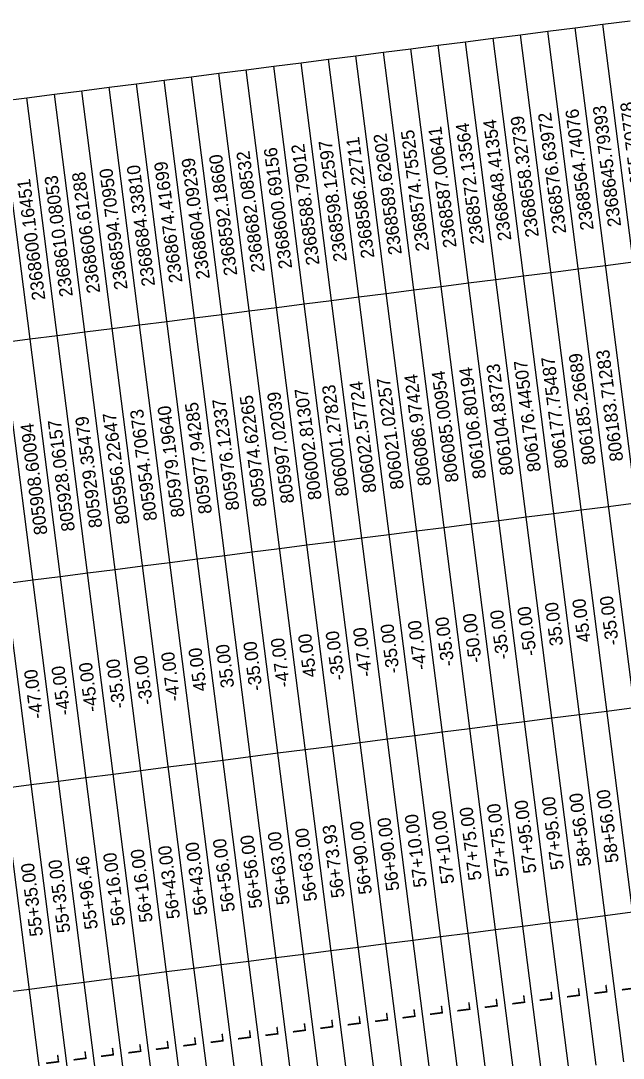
# Model space of a CAD drawing. Extents: x 2364621 to 2374814, y 792603 to 806745.
# Drawn here: x 2367039 to 2368118, y 803235 to 805094 of the extents above; entities that cross this region are included whole.
import ezdxf

# ---------------------------------------------------------------- set-up
doc = ezdxf.new("R2010")
doc.units = 0
doc.layers.add('CTL Sheet Table Cell', color=7, linetype='Continuous')
doc.layers.add('CTL Sheet Text', color=7, linetype='Continuous')

msp = doc.modelspace()

# ---------------------------------------------------------------- linework, layer by layer
at = {"layer": 'CTL Sheet Table Cell'}
for p, q in [((2368081.5, 805087.2), (2368130.6, 805093.5)), ((2367934.2, 805068.4), (2367983.3, 805074.7)), ((2367983.3, 805074.7), (2368032.4, 805081)), ((2368217.5, 803241), (2367983.3, 805074.7)), ((2368032.4, 805081), (2368081.5, 805087.2)), ((2368266.6, 803247.2), (2368032.4, 805081)), ((2368315.7, 803253.5), (2368081.5, 805087.2)), ((2367786.8, 805049.6), (2367835.9, 805055.9)), ((2367835.9, 805055.9), (2367885.1, 805062.2)), ((2368070.1, 803222.1), (2367835.9, 805055.9)), ((2367885.1, 805062.2), (2367934.2, 805068.4)), ((2368119.3, 803228.4), (2367885.1, 805062.2)), ((2368168.4, 803234.7), (2367934.2, 805068.4)), ((2367639.5, 805030.8), (2367688.6, 805037.1)), ((2367688.6, 805037.1), (2367737.7, 805043.3)), ((2367922.8, 803203.3), (2367688.6, 805037.1)), ((2367737.7, 805043.3), (2367786.8, 805049.6)), ((2367971.9, 803209.6), (2367737.7, 805043.3)), ((2368021, 803215.9), (2367786.8, 805049.6)), ((2367492.1, 805012), (2367541.2, 805018.2)), ((2367541.2, 805018.2), (2367590.3, 805024.5)), ((2367775.4, 803184.5), (2367541.2, 805018.2)), ((2367590.3, 805024.5), (2367639.5, 805030.8)), ((2367824.5, 803190.8), (2367590.3, 805024.5)), ((2367873.7, 803197), (2367639.5, 805030.8)), ((2367344.8, 804993.1), (2367393.9, 804999.4)), ((2367393.9, 804999.4), (2367443, 805005.7)), ((2367628.1, 803165.7), (2367393.9, 804999.4)), ((2367443, 805005.7), (2367492.1, 805012)), ((2367677.2, 803172), (2367443, 805005.7)), ((2367726.3, 803178.2), (2367492.1, 805012)), ((2367197.4, 804974.3), (2367246.5, 804980.6)), ((2367246.5, 804980.6), (2367295.6, 804986.9)), ((2367480.7, 803146.9), (2367246.5, 804980.6)), ((2367295.6, 804986.9), (2367344.8, 804993.1)), ((2367529.8, 803153.1), (2367295.6, 804986.9)), ((2367579, 803159.4), (2367344.8, 804993.1)), ((2367050, 804955.5), (2367099.2, 804961.8)), ((2367099.2, 804961.8), (2367148.3, 804968.1)), ((2367333.4, 803128), (2367099.2, 804961.8)), ((2367148.3, 804968.1), (2367197.4, 804974.3)), ((2367382.5, 803134.3), (2367148.3, 804968.1)), ((2367431.6, 803140.6), (2367197.4, 804974.3)), ((2367186, 803109.2), (2366951.8, 804943)), ((2367000.9, 804949.2), (2367050, 804955.5)), ((2367235.1, 803115.5), (2367000.9, 804949.2)), ((2367284.2, 803121.8), (2367050, 804955.5)), ((2367087.8, 803096.7), (2366853.6, 804930.4)), ((2367136.9, 803102.9), (2366902.7, 804936.7)), ((2368086.8, 804655.3), (2368135.9, 804661.6)), ((2367939.4, 804636.5), (2367988.5, 804642.7)), ((2367988.5, 804642.7), (2368037.7, 804649)), ((2368037.7, 804649), (2368086.8, 804655.3)), ((2367841.2, 804623.9), (2367890.3, 804630.2)), ((2367890.3, 804630.2), (2367939.4, 804636.5)), ((2367693.8, 804605.1), (2367742.9, 804611.4)), ((2367742.9, 804611.4), (2367792.1, 804617.6)), ((2367792.1, 804617.6), (2367841.2, 804623.9)), ((2367546.5, 804586.3), (2367595.6, 804592.5)), ((2367595.6, 804592.5), (2367644.7, 804598.8)), ((2367644.7, 804598.8), (2367693.8, 804605.1)), ((2367399.1, 804567.5), (2367448.2, 804573.7)), ((2367448.2, 804573.7), (2367497.4, 804580)), ((2367497.4, 804580), (2367546.5, 804586.3)), ((2367251.8, 804548.6), (2367300.9, 804554.9)), ((2367300.9, 804554.9), (2367350, 804561.2)), ((2367350, 804561.2), (2367399.1, 804567.5)), ((2367104.4, 804529.8), (2367153.5, 804536.1)), ((2367153.5, 804536.1), (2367202.7, 804542.4)), ((2367202.7, 804542.4), (2367251.8, 804548.6)), ((2367006.2, 804517.3), (2367055.3, 804523.5)), ((2367055.3, 804523.5), (2367104.4, 804529.8)), ((2367993.8, 804210.8), (2368042.9, 804217)), ((2368042.9, 804217), (2368092, 804223.3)), ((2368092, 804223.3), (2368141.1, 804229.6)), ((2367846.4, 804192), (2367895.6, 804198.2)), ((2367895.6, 804198.2), (2367944.7, 804204.5)), ((2367944.7, 804204.5), (2367993.8, 804210.8)), ((2367699.1, 804173.1), (2367748.2, 804179.4)), ((2367748.2, 804179.4), (2367797.3, 804185.7)), ((2367797.3, 804185.7), (2367846.4, 804192)), ((2367551.7, 804154.3), (2367600.8, 804160.6)), ((2367600.8, 804160.6), (2367650, 804166.9)), ((2367650, 804166.9), (2367699.1, 804173.1)), ((2367404.4, 804135.5), (2367453.5, 804141.8)), ((2367453.5, 804141.8), (2367502.6, 804148)), ((2367502.6, 804148), (2367551.7, 804154.3)), ((2367257, 804116.7), (2367306.1, 804122.9)), ((2367306.1, 804122.9), (2367355.3, 804129.2)), ((2367355.3, 804129.2), (2367404.4, 804135.5)), ((2367109.7, 804097.9), (2367158.8, 804104.1)), ((2367158.8, 804104.1), (2367207.9, 804110.4)), ((2367207.9, 804110.4), (2367257, 804116.7)), ((2367011.4, 804085.3), (2367060.5, 804091.6)), ((2367060.5, 804091.6), (2367109.7, 804097.9)), ((2368088.9, 803856.8), (2368138, 803863.1)), ((2367941.6, 803838), (2367990.7, 803844.3)), ((2367990.7, 803844.3), (2368039.8, 803850.6)), ((2368039.8, 803850.6), (2368088.9, 803856.8)), ((2367794.2, 803819.2), (2367843.3, 803825.5)), ((2367843.3, 803825.5), (2367892.4, 803831.8)), ((2367892.4, 803831.8), (2367941.6, 803838)), ((2367646.8, 803800.4), (2367696, 803806.7)), ((2367696, 803806.7), (2367745.1, 803812.9)), ((2367745.1, 803812.9), (2367794.2, 803819.2)), ((2367499.5, 803781.6), (2367548.6, 803787.8)), ((2367548.6, 803787.8), (2367597.7, 803794.1)), ((2367597.7, 803794.1), (2367646.8, 803800.4)), ((2367352.1, 803762.7), (2367401.3, 803769)), ((2367401.3, 803769), (2367450.4, 803775.3)), ((2367450.4, 803775.3), (2367499.5, 803781.6)), ((2367253.9, 803750.2), (2367303, 803756.5)), ((2367303, 803756.5), (2367352.1, 803762.7)), ((2367106.6, 803731.4), (2367155.7, 803737.7)), ((2367155.7, 803737.7), (2367204.8, 803743.9)), ((2367204.8, 803743.9), (2367253.9, 803750.2)), ((2367008.3, 803718.8), (2367057.4, 803725.1)), ((2367057.4, 803725.1), (2367106.6, 803731.4)), ((2368036.7, 803484.1), (2368085.8, 803490.4)), ((2368085.8, 803490.4), (2368134.9, 803496.7)), ((2367889.3, 803465.3), (2367938.4, 803471.6)), ((2367938.4, 803471.6), (2367987.6, 803477.8)), ((2367987.6, 803477.8), (2368036.7, 803484.1)), ((2367791.1, 803452.7), (2367840.2, 803459)), ((2367840.2, 803459), (2367889.3, 803465.3)), ((2367643.7, 803433.9), (2367692.9, 803440.2)), ((2367692.9, 803440.2), (2367742, 803446.5)), ((2367742, 803446.5), (2367791.1, 803452.7)), ((2367496.4, 803415.1), (2367545.5, 803421.4)), ((2367545.5, 803421.4), (2367594.6, 803427.6)), ((2367594.6, 803427.6), (2367643.7, 803433.9)), ((2367349, 803396.3), (2367398.1, 803402.6)), ((2367398.1, 803402.6), (2367447.3, 803408.8)), ((2367447.3, 803408.8), (2367496.4, 803415.1)), ((2367201.7, 803377.5), (2367250.8, 803383.7)), ((2367250.8, 803383.7), (2367299.9, 803390)), ((2367299.9, 803390), (2367349, 803396.3)), ((2367054.3, 803358.6), (2367103.4, 803364.9)), ((2367103.4, 803364.9), (2367152.6, 803371.2)), ((2367152.6, 803371.2), (2367201.7, 803377.5)), ((2367005.2, 803352.4), (2367054.3, 803358.6))]:
    msp.add_line(p, q, dxfattribs=at)

# ---------------------------------------------------------------- texts
at = {"layer": 'CTL Sheet Text'}
for s, height, p in [('2368645.79393', 23.579, (2368114.6, 804725.8)), ('2368655.70778', 23.579, (2368163.7, 804732.1)), ('2368658.32739', 23.579, (2367967.3, 804707)), ('2368576.63972', 23.579, (2368016.4, 804713.2)), ('2368564.74076', 23.579, (2368065.5, 804719.5)), ('2368587.00641', 23.579, (2367819.9, 804688.1)), ('2368572.13564', 23.579, (2367869, 804694.4)), ('2368648.41354', 23.579, (2367918.1, 804700.7)), ('2368586.22711', 23.579, (2367672.6, 804669.3)), ('2368589.62602', 23.579, (2367721.7, 804675.6)), ('2368574.75525', 23.579, (2367770.8, 804681.9)), ('2368600.69156', 23.579, (2367525.2, 804650.5)), ('2368588.79012', 23.579, (2367574.3, 804656.8)), ('2368598.12597', 23.579, (2367623.4, 804663.1)), ('2368592.18660', 23.579, (2367427, 804638)), ('2368682.08532', 23.579, (2367476.1, 804644.2)), ('2368684.33810', 23.579, (2367279.6, 804619.1)), ('2368674.41699', 23.579, (2367328.7, 804625.4)), ('2368604.09239', 23.579, (2367377.8, 804631.7)), ('2368600.16451', 23.579, (2367083.1, 804594)), ('2368610.08053', 23.579, (2367132.3, 804600.3)), ('2368606.61288', 23.579, (2367181.4, 804606.6)), ('2368594.70950', 23.579, (2367230.5, 804612.9)), ('806185.26689', 23.579, (2368069.3, 804299.2)), ('806183.71283', 23.579, (2368118.4, 804305.4)), ('806104.83723', 23.579, (2367921.9, 804280.3)), ('806176.44507', 23.579, (2367971, 804286.6)), ('806177.75487', 23.579, (2368020.1, 804292.9)), ('806086.97424', 23.579, (2367774.6, 804261.5)), ('806085.00954', 23.579, (2367823.7, 804267.8)), ('806106.80194', 23.579, (2367872.8, 804274.1)), ('806001.27823', 23.579, (2367627.2, 804242.7)), ('806022.57724', 23.579, (2367676.3, 804249)), ('806021.02257', 23.579, (2367725.4, 804255.2)), ('805974.62265', 23.579, (2367479.8, 804223.9)), ('805997.02039', 23.579, (2367529, 804230.2)), ('806002.81307', 23.579, (2367578.1, 804236.4)), ('805979.19640', 23.579, (2367332.5, 804205.1)), ('805977.94285', 23.579, (2367381.6, 804211.3)), ('805976.12337', 23.579, (2367430.7, 804217.6)), ('805929.35479', 23.579, (2367185.1, 804186.2)), ('805956.22647', 23.579, (2367234.3, 804192.5)), ('805954.70673', 23.579, (2367283.4, 804198.8)), ('805908.60094', 23.579, (2367086.9, 804173.7)), ('805928.06157', 23.579, (2367136, 804180)), ('35.00', 23.58, (2368010.8, 803974.9)), ('45.00', 23.58, (2368060, 803981.2)), ('-35.00', 23.58, (2368110.6, 803975.8)), ('-50.00', 23.58, (2367865, 803944.5)), ('-35.00', 23.58, (2367914.1, 803950.7)), ('-50.00', 23.58, (2367963.2, 803957)), ('-35.00', 23.58, (2367717.6, 803925.6)), ('-47.00', 23.58, (2367766.7, 803931.9)), ('-35.00', 23.58, (2367815.9, 803938.2)), ('45.00', 23.58, (2367568.8, 803918.4)), ('-35.00', 23.58, (2367619.4, 803913.1)), ('-47.00', 23.58, (2367668.5, 803919.4)), ('35.00', 23.58, (2367421.4, 803899.6)), ('-35.00', 23.58, (2367472, 803894.3)), ('-47.00', 23.58, (2367521.1, 803900.5)), ('-35.00', 23.58, (2367275.6, 803869.2)), ('-47.00', 23.58, (2367324.7, 803875.5)), ('45.00', 23.58, (2367372.3, 803893.3)), ('-45.00', 23.58, (2367128.2, 803850.4)), ('-45.00', 23.58, (2367177.3, 803856.6)), ('-35.00', 23.58, (2367226.4, 803862.9)), ('-47.00', 23.58, (2367079.1, 803844.1)), ('58+56.00', 23.58, (2368110.4, 803586.2)), ('57+95.00', 23.58, (2367963.1, 803567.3)), ('57+95.00', 23.58, (2368012.2, 803573.6)), ('58+56.00', 23.58, (2368061.3, 803579.9)), ('57+10.00', 23.58, (2367815.7, 803548.5)), ('57+75.00', 23.58, (2367864.8, 803554.8)), ('57+75.00', 23.58, (2367913.9, 803561.1)), ('56+90.00', 23.58, (2367668.3, 803529.7)), ('56+90.00', 23.58, (2367717.5, 803536)), ('57+10.00', 23.58, (2367766.6, 803542.2)), ('56+63.00', 23.58, (2367521, 803510.9)), ('56+63.00', 23.58, (2367570.1, 803517.1)), ('56+73.93', 23.58, (2367619.2, 803523.4)), ('56+43.00', 23.58, (2367373.6, 803492.1)), ('56+56.00', 23.58, (2367422.8, 803498.3)), ('56+56.00', 23.58, (2367471.9, 803504.6)), ('56+16.00', 23.58, (2367226.3, 803473.2)), ('56+16.00', 23.58, (2367275.4, 803479.5)), ('56+43.00', 23.58, (2367324.5, 803485.8)), ('55+35.00', 23.58, (2367078.9, 803454.4)), ('55+35.00', 23.58, (2367128, 803460.7)), ('55+96.46', 23.58, (2367177.2, 803467)), ('L', 23.6, (2368041.5, 803343.7)), ('L', 23.6, (2368090.6, 803350)), ('L', 23.6, (2368139.8, 803356.3)), ('L', 23.6, (2367943.3, 803331.2)), ('L', 23.6, (2367992.4, 803337.5)), ('L', 23.6, (2367795.9, 803312.4)), ('L', 23.6, (2367845.1, 803318.7)), ('L', 23.6, (2367894.2, 803324.9)), ('L', 23.6, (2367648.6, 803293.6)), ('L', 23.6, (2367697.7, 803299.8)), ('L', 23.6, (2367746.8, 803306.1)), ('L', 23.6, (2367501.2, 803274.7)), ('L', 23.6, (2367550.4, 803281)), ('L', 23.6, (2367599.5, 803287.3)), ('L', 23.6, (2367353.9, 803255.9)), ('L', 23.6, (2367403, 803262.2)), ('L', 23.6, (2367452.1, 803268.5)), ('L', 23.6, (2367206.5, 803237.1)), ('L', 23.6, (2367255.6, 803243.4)), ('L', 23.6, (2367304.8, 803249.6)), ('L', 23.6, (2367108.3, 803224.6)), ('L', 23.6, (2367157.4, 803230.8))]:
    msp.add_text(s, height=height, rotation=97.2784, dxfattribs=at).set_placement(p)

doc.saveas('drawing.dxf')
